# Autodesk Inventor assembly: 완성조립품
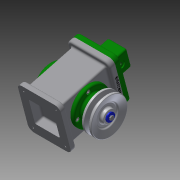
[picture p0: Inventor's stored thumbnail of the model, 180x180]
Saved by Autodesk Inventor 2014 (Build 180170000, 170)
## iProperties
Created: 2017-08
Part Number: 완성조립품
Document SubType Name: Assembly
Designer: user
Author: user
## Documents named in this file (18)
- C:\Users\user\Desktop\완성조립품.iam
- C:\Users\user\Desktop\본체.ipt
- C:\Users\user\Desktop\470808V1021\E-링.ipt
- C:\Users\user\Desktop\470808V1021\V-벨트풀리.ipt
- C:\Users\user\Desktop\470808V1021\덮개.ipt
- C:\Users\user\Desktop\470808V1021\뒤커버.ipt
- C:\Users\user\Desktop\470808V1021\링크.ipt
- C:\Users\user\Desktop\470808V1021\베어링 17 x 40 x 12.ipt
- C:\Users\user\Desktop\470808V1021\볼트 M4 x 8.ipt
- C:\Users\user\Desktop\470808V1021\볼트 M4 x 10.ipt
- C:\Users\user\Desktop\470808V1021\슬라이더.ipt
- C:\Users\user\Desktop\470808V1021\앞커버.ipt
- C:\Users\user\Desktop\470808V1021\오일 실 17 30 8.ipt
- C:\Users\user\Desktop\470808V1021\와셔 4x16.ipt
- C:\Users\user\Desktop\470808V1021\클레비스 핀 6 x 22.ipt
- 클레비스 핀 6 x 22.ipt
- C:\Users\user\Desktop\470808V1021\키 4 x 4 x 12.ipt
- C:\Users\user\Desktop\470808V1021\편심축.ipt
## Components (2 placed, 2 different names)
1. E-링:1 — Mate:45, Mate:46
2. V-벨트풀리:1 — Mate:4, Mate:5, Mate:6
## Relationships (5: Mate 5)
- Mate:4: V-벨트풀리:1
- Mate:5: V-벨트풀리:1
- Mate:6: V-벨트풀리:1
- Mate:45: E-링:1
- Mate:46: E-링:1
